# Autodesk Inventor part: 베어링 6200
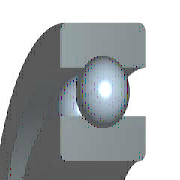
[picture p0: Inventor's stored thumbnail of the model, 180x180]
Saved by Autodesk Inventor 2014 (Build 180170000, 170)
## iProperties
Created: 2012-02
Part Number: 베어링 6200
Material: 강철, 연강
Description: 깊은 그루브 볼 베어링
Document SubType Name: Modeling
Standard: KS B 2023
Designer: mduedu
Standards Organization: KS
Language: ko-KR
Size Designation: 6200 - 10 x 30 x 9
Categories: <MemberInstance><Categories><Category DisplayName="샤프트 부품" InternalName="7f7aeb1f-a693-4053-b835-cee3144e0d98" Mnemonic="SHFT"><Category DisplayName="베어링" Inter
Density: 1 g/cm^3
Appearance: 노란색
IsCustomPart: 1
Author: mduedu
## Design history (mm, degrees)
sketch "스케치" dims "d0" = 5.2 (= -0.26 x WD + 0.26 x BD)
  geometry: L1 (1.9, 10)-(7.1, 10); L2 (4.5, 10)-(4.5, 7.4); L3 (4.5, 10)-(4.5, 12.6); L4 (2.568, 8.26)-(0, 8.26); L5 (0, 5)-(9, 5); L6 (2.568, 11.74)-(0, 11.74); L7 (0, 15)-(9, 15); L8 (9, 5)-(9, 8.26); L9 (6.432, 8.26)-(9, 8.26); L10 (6.432, 11.74)-(9, 11.74); L11 (9, 15)-(9, 11.74); L12 (-1.4, 0)-(8.4, 0) reference; L13 (0, -0.3)-(0, 5.3) reference
  constraints: 22 end point, 4 point on line, 2 collinear, 2 perpendicular, 2 symmetric about line, 1 midpoint, 1 parallel, 14 other
  dimensions: "d9" = 10 diameter of L5 L12 (= WD); "d11" = 30 diameter of L7 L12 (= BD); "d12" = 9 distance between parallel lines of L8 L13 (= KB); "d13" = 16.52 diameter of L9 L12 (= 0.326 x BD + 0.674 x WD)
revolve "본체" stored, may be unused: angle "d6" = 90 deg
revolve "볼" stored, may be unused: angle "d7" = 90 deg
pattern_circular "IDS_ARRAYBALL[SIMPL:T]" dims angle "d3" = 360 deg
body "Solid1"
fillet "모깎기1" dims "d1" = 0.6 (= KRS)
other parameters: "WD" = 10 [user parameter; used in 5 equation terms], "BD" = 30 [user parameter; used in 5 equation terms], "KB" = 9 [user parameter; used in 1 equation term], "KRS" = 0.6 [user parameter; used in 1 equation term], "d4" = 0, "d5" = 0, "d8" = 0, "d14" = 0, "d15" = 0, "BBA" = 0 [user parameter], "BC0" = 2360000 [user parameter], "BC" = 5070000 [user parameter], "BR" = 15 (= 0.5 x BD) [user parameter], "WR" = 5 (= 0.5 x WD) [user parameter]
